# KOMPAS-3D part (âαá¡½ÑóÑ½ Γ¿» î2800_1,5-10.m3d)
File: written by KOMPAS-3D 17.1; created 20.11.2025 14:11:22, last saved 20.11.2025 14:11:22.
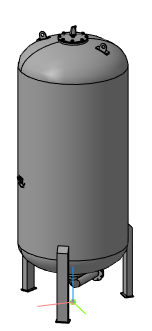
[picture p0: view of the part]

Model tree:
1. Операция без истории:1

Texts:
  REVIT MATERIAL OVERRIDDEN
  REVIT MATERIAL ID
  REVIT SUBCATEGORY ID
  REVIT CATEGORY ID
  REVIT ELEMENT ID
  REVIT BREP TAG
